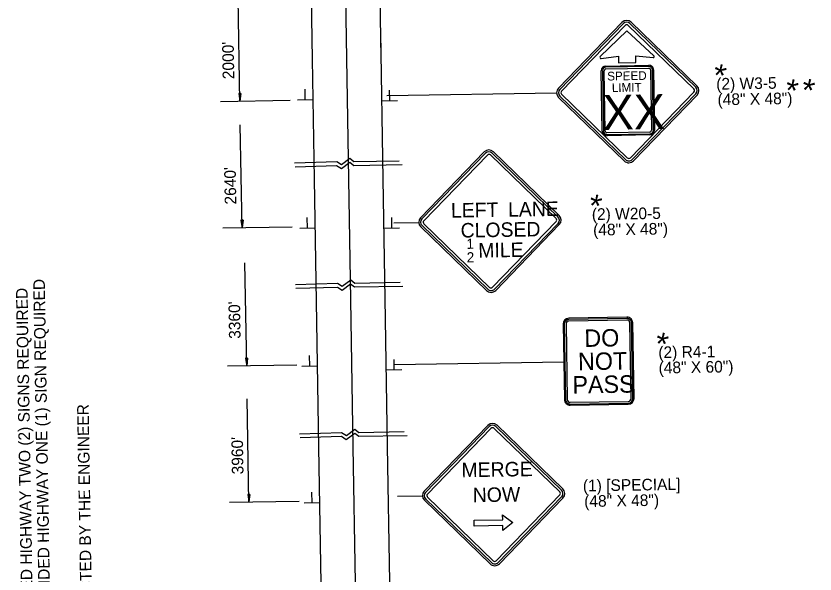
# Model space of a CAD drawing. Extents: x 1676639 to 1677883, y 226447 to 231777.
# Drawn here: x 1677053.1 to 1677466.1, y 226686.5 to 226975 of the extents above; entities that cross this region are included whole.
import ezdxf

# ---------------------------------------------------------------- set-up
doc = ezdxf.new("R2010")
doc.units = 0
for name, color, linetype in [('Default', 7, 'Continuous'), ('P_TC_Signs_Permanent', 7, 'Continuous'), ('P_TC_Signs_Temporary', 7, 'Continuous'), ('R_Annotation', 7, 'Continuous'), ('R_MOT', 7, 'Continuous')]:
    doc.layers.add(name, color=color, linetype=linetype)

msp = doc.modelspace()

# ---------------------------------------------------------------- linework, layer by layer
at = {"layer": 'Default'}
for p, q in [((1677241.81, 226953.29), (1677240.19, 227050.97)), ((1677206.35, 226952.71), (1677204.89, 227041.03)), ((1677224.08, 226953), (1677222.62, 227041.32)), ((1677168.85, 226930.99), (1677167.97, 226984.21)), ((1677242.85, 226890.55), (1677241.59, 226966.37)), ((1677207.38, 226890.65), (1677206.35, 226952.71)), ((1677225.12, 226890.6), (1677224.08, 226953)), ((1677169.36, 226934.82), (1677168.21, 226934.81)), ((1677168.21, 226934.81), (1677168.85, 226930.99)), ((1677168.31, 226934.81), (1677168.84, 226931.63)), ((1677168.4, 226934.81), (1677168.83, 226932.29)), ((1677168.5, 226934.81), (1677168.82, 226932.92)), ((1677168.6, 226934.81), (1677168.8, 226933.57)), ((1677168.69, 226934.81), (1677168.79, 226934.21)), ((1677168.87, 226934.82), (1677168.79, 226934.21)), ((1677168.97, 226934.82), (1677168.8, 226933.57)), ((1677169.07, 226934.82), (1677168.82, 226932.92)), ((1677169.16, 226934.82), (1677168.83, 226932.29)), ((1677169.26, 226934.82), (1677168.84, 226931.63)), ((1677169.36, 226934.82), (1677168.85, 226930.99)), ((1677202.65, 226931.67), (1677202.56, 226937.11)), ((1677246.29, 226931.1), (1677246.2, 226936.55)), ((1677158.86, 226930.82), (1677194.77, 226931.42)), ((1677206.62, 226931.62), (1677198.64, 226931.48)), ((1677250.26, 226931.05), (1677242.28, 226930.92)), ((1677169.93, 226865.56), (1677169.05, 226918.78)), ((1677208.43, 226827.45), (1677207.38, 226890.65)), ((1677226.15, 226828.21), (1677225.12, 226890.6)), ((1677243.87, 226828.97), (1677242.85, 226890.55)), ((1677170.44, 226869.39), (1677169.29, 226869.37)), ((1677169.29, 226869.37), (1677169.93, 226865.56)), ((1677169.39, 226869.37), (1677169.92, 226866.2)), ((1677169.49, 226869.38), (1677169.91, 226866.85)), ((1677169.58, 226869.38), (1677169.9, 226867.49)), ((1677169.68, 226869.38), (1677169.89, 226868.14)), ((1677169.78, 226869.38), (1677169.88, 226868.78)), ((1677169.96, 226869.38), (1677169.88, 226868.78)), ((1677170.05, 226869.38), (1677169.89, 226868.14)), ((1677170.15, 226869.39), (1677169.9, 226867.49)), ((1677170.25, 226869.39), (1677169.91, 226866.85)), ((1677170.35, 226869.39), (1677169.92, 226866.2)), ((1677170.44, 226869.39), (1677169.93, 226865.56)), ((1677203.75, 226865.31), (1677203.66, 226870.75)), ((1677247.38, 226865.34), (1677247.29, 226870.79)), ((1677159.95, 226865.39), (1677195.85, 226865.99)), ((1677207.72, 226865.25), (1677199.74, 226865.12)), ((1677251.35, 226865.29), (1677243.37, 226865.16)), ((1677172.34, 226794.22), (1677171.46, 226847.45)), ((1677209.68, 226752.04), (1677208.43, 226827.45)), ((1677227.41, 226752.34), (1677226.15, 226828.21)), ((1677245.14, 226752.63), (1677243.87, 226828.97)), ((1677204.93, 226793.95), (1677204.84, 226799.4)), ((1677162.35, 226794.06), (1677198.26, 226794.65)), ((1677172.85, 226798.06), (1677171.7, 226798.04)), ((1677171.7, 226798.04), (1677172.34, 226794.22)), ((1677171.8, 226798.04), (1677172.33, 226794.86)), ((1677171.89, 226798.04), (1677172.32, 226795.52)), ((1677171.99, 226798.04), (1677172.31, 226796.16)), ((1677172.09, 226798.04), (1677172.3, 226796.8)), ((1677172.18, 226798.05), (1677172.28, 226797.44)), ((1677172.36, 226798.05), (1677172.28, 226797.44)), ((1677172.46, 226798.05), (1677172.3, 226796.8)), ((1677172.56, 226798.05), (1677172.31, 226796.16)), ((1677172.66, 226798.05), (1677172.32, 226795.52)), ((1677172.75, 226798.06), (1677172.33, 226794.86)), ((1677172.85, 226798.06), (1677172.34, 226794.22)), ((1677248.59, 226792.05), (1677248.5, 226797.49)), ((1677208.9, 226793.9), (1677200.92, 226793.77)), ((1677252.56, 226792), (1677244.59, 226791.86)), ((1677173.5, 226723.85), (1677172.62, 226777.07)), ((1677210.84, 226681.67), (1677209.68, 226752.04)), ((1677228.57, 226681.96), (1677227.41, 226752.34)), ((1677246.3, 226682.26), (1677245.14, 226752.63)), ((1677206.1, 226723.33), (1677206.01, 226728.78)), ((1677163.52, 226723.68), (1677199.43, 226724.28)), ((1677174.01, 226727.68), (1677172.87, 226727.66)), ((1677172.87, 226727.66), (1677173.5, 226723.85)), ((1677172.96, 226727.67), (1677173.49, 226724.49)), ((1677173.06, 226727.67), (1677173.48, 226725.15)), ((1677173.16, 226727.67), (1677173.47, 226725.78)), ((1677173.25, 226727.67), (1677173.46, 226726.43)), ((1677173.35, 226727.67), (1677173.45, 226727.07)), ((1677173.53, 226727.68), (1677173.45, 226727.07)), ((1677173.63, 226727.68), (1677173.46, 226726.43)), ((1677173.73, 226727.68), (1677173.47, 226725.78)), ((1677173.82, 226727.68), (1677173.48, 226725.15)), ((1677173.92, 226727.68), (1677173.49, 226724.49)), ((1677174.01, 226727.68), (1677173.5, 226723.85)), ((1677210.07, 226723.28), (1677202.09, 226723.15))]:
    msp.add_line(p, q, dxfattribs=at)
for points in [[(1677197.14, 226899.07), (1677218.87, 226899.76), (1677221.36, 226898.15), (1677225.72, 226901.45), (1677227.79, 226899.78), (1677251.21, 226900.17)], [(1677197.37, 226897.04), (1677218.82, 226897.72), (1677221.31, 226896.11), (1677225.67, 226899.41), (1677227.74, 226897.74), (1677252.68, 226898.15)], [(1677197.52, 226836.23), (1677219.24, 226836.92), (1677221.73, 226835.3), (1677226.09, 226838.6), (1677228.16, 226836.94), (1677251.58, 226837.32)], [(1677197.75, 226834.2), (1677219.19, 226834.88), (1677221.68, 226833.27), (1677226.04, 226836.57), (1677228.11, 226834.9), (1677253.05, 226835.31)], [(1677199.68, 226759.06), (1677221.41, 226759.75), (1677223.9, 226758.14), (1677228.26, 226761.44), (1677230.32, 226759.77), (1677253.75, 226760.16)], [(1677199.91, 226757.03), (1677221.35, 226757.71), (1677223.84, 226756.1), (1677228.21, 226759.4), (1677230.27, 226757.73), (1677255.22, 226758.14)]]:
    msp.add_lwpolyline(points, dxfattribs=at)
at = {"layer": 'P_TC_Signs_Permanent'}
for p, q in [((1677405.03, 226938.84), (1677371.07, 226971.7)), ((1677366.3, 226971.62), (1677333.45, 226937.66)), ((1677366.98, 226970.97), (1677334.12, 226937.01)), ((1677367.92, 226970.05), (1677335.07, 226936.09)), ((1677403.47, 226937.23), (1677369.51, 226970.08)), ((1677404.38, 226938.17), (1677370.42, 226971.02)), ((1677357.96, 226949.09), (1677380.16, 226949.45)), ((1677382.6, 226947.09), (1677383.11, 226915.9)), ((1677356.12, 226915.45), (1677355.6, 226946.65)), ((1677335.09, 226934.5), (1677369.05, 226901.65)), ((1677370.64, 226901.68), (1677403.5, 226935.64)), ((1677371.59, 226900.76), (1677404.44, 226934.72)), ((1677333.53, 226932.89), (1677367.49, 226900.03)), ((1677334.18, 226933.56), (1677368.14, 226900.71)), ((1677372.26, 226900.11), (1677405.11, 226934.07)), ((1677380.76, 226913.46), (1677358.56, 226913.09)), ((1677368.83, 226819.27), (1677338.83, 226818.77)), ((1677335.88, 226815.72), (1677336.53, 226776.73)), ((1677336.48, 226815.73), (1677337.13, 226776.74)), ((1677337.38, 226815.75), (1677338.03, 226776.75)), ((1677368.84, 226818.67), (1677338.84, 226818.17)), ((1677368.85, 226817.77), (1677338.86, 226817.27)), ((1677371.02, 226777.3), (1677370.38, 226816.29)), ((1677371.92, 226777.31), (1677371.28, 226816.31)), ((1677372.52, 226777.32), (1677371.88, 226816.32)), ((1677339.55, 226775.28), (1677369.55, 226775.77)), ((1677339.57, 226774.38), (1677369.56, 226774.87)), ((1677339.58, 226773.78), (1677369.57, 226774.27))]:
    msp.add_line(p, q, dxfattribs=at)
for points in [[(1677382.82, 226954.41), (1677368.73, 226967.27), (1677355.06, 226953.95)], [(1677355.54, 226952.99), (1677364.48, 226954.26), (1677364.54, 226950.7), (1677373.53, 226950.84), (1677373.48, 226954.4), (1677382.38, 226953.44)], [(1677380.17, 226948.85), (1677369.07, 226948.67), (1677357.97, 226948.49)], [(1677357.99, 226947.59), (1677369.08, 226947.77), (1677380.18, 226947.95)], [(1677381.1, 226947.07), (1677381.62, 226915.87)], [(1677382.52, 226915.89), (1677382, 226947.08)], [(1677356.2, 226946.66), (1677356.72, 226915.46)], [(1677357.62, 226915.48), (1677357.1, 226946.67)], [(1677380.73, 226914.96), (1677358.53, 226914.59)], [(1677358.55, 226913.69), (1677380.75, 226914.06)]]:
    msp.add_lwpolyline(points, dxfattribs=at)
for centre, radius, start, end in [((1677368.73, 226969.27), 3.38, 45.9497, 135.9497), ((1677368.73, 226969.27), 2.44, 45.9497, 135.9497), ((1677368.73, 226969.27), 1.13, 45.9497, 135.9497), ((1677355.46, 226953.55), 0.563, 134.2614, 278.0747), ((1677382.44, 226954), 0.563, 263.8247, 47.6381), ((1677358, 226946.69), 2.4, 90.9497, 180.9497), ((1677358, 226946.69), 1.8, 90.9497, 180.9497), ((1677358, 226946.69), 0.9, 90.9497, 180.9497), ((1677380.2, 226947.05), 2.4, 0.9497, 90.9497), ((1677380.2, 226947.05), 1.8, 0.9497, 90.9497), ((1677380.2, 226947.05), 0.9, 0.9497, 90.9497), ((1677402.69, 226936.42), 3.38, 315.9497, 45.9497), ((1677335.88, 226935.31), 3.38, 135.9497, 225.9497), ((1677335.88, 226935.31), 2.44, 135.9497, 225.9497), ((1677335.88, 226935.31), 1.13, 135.9497, 225.9497), ((1677402.69, 226936.42), 1.13, 315.9497, 45.9497), ((1677402.69, 226936.42), 2.44, 315.9497, 45.9497), ((1677358.52, 226915.49), 2.4, 180.9497, 270.9497), ((1677358.52, 226915.49), 1.8, 180.9497, 270.9497), ((1677358.52, 226915.49), 0.9, 180.9497, 270.9497), ((1677380.72, 226915.86), 0.9, 270.9497, 0.9497), ((1677380.72, 226915.86), 1.8, 270.9497, 0.9497), ((1677380.72, 226915.86), 2.4, 270.9497, 0.9497), ((1677369.84, 226902.46), 1.13, 225.9497, 315.9497), ((1677369.84, 226902.46), 3.38, 225.9497, 315.9497), ((1677369.84, 226902.46), 2.44, 225.9497, 315.9497), ((1677368.88, 226816.27), 3, 0.9497, 90.9497), ((1677338.88, 226815.77), 3, 90.9497, 180.9497), ((1677338.88, 226815.77), 2.4, 90.9497, 180.9497), ((1677338.88, 226815.77), 1.5, 90.9497, 180.9497), ((1677368.88, 226816.27), 2.4, 0.9497, 90.9497), ((1677368.88, 226816.27), 1.5, 0.9497, 90.9497), ((1677339.53, 226776.78), 3, 180.9497, 270.9497), ((1677339.53, 226776.78), 2.4, 180.9497, 270.9497), ((1677339.53, 226776.78), 1.5, 180.9497, 270.9497), ((1677369.52, 226777.27), 1.5, 270.9497, 0.9497), ((1677369.52, 226777.27), 2.4, 270.9497, 0.9497), ((1677369.52, 226777.27), 3, 270.9497, 0.9497)]:
    msp.add_arc(centre, radius, start, end, dxfattribs=at)
at = {"layer": 'P_TC_Signs_Temporary'}
for p, q in [((1677262.24, 226870.7), (1677295.09, 226904.66)), ((1677262.91, 226870.04), (1677295.77, 226904)), ((1677263.86, 226869.13), (1677296.71, 226903.09)), ((1677298.3, 226903.12), (1677332.26, 226870.27)), ((1677299.21, 226904.06), (1677333.17, 226871.21)), ((1677299.86, 226904.74), (1677333.82, 226871.88)), ((1677332.29, 226868.68), (1677299.43, 226834.72)), ((1677296.28, 226833.07), (1677262.32, 226865.92)), ((1677296.93, 226833.75), (1677262.97, 226866.6)), ((1677297.84, 226834.69), (1677263.88, 226867.54)), ((1677333.23, 226867.76), (1677300.38, 226833.8)), ((1677333.9, 226867.11), (1677301.05, 226833.15)), ((1677296.98, 226763.37), (1677264.13, 226729.41)), ((1677297.66, 226762.71), (1677264.8, 226728.75)), ((1677298.6, 226761.8), (1677265.75, 226727.84)), ((1677334.15, 226728.98), (1677300.19, 226761.83)), ((1677335.06, 226729.92), (1677301.1, 226762.77)), ((1677335.72, 226730.59), (1677301.76, 226763.45)), ((1677264.21, 226724.63), (1677298.17, 226691.78)), ((1677264.86, 226725.31), (1677298.82, 226692.46)), ((1677265.77, 226726.25), (1677299.73, 226693.4)), ((1677301.32, 226693.43), (1677334.18, 226727.39)), ((1677302.27, 226692.51), (1677335.12, 226726.47)), ((1677302.94, 226691.86), (1677335.79, 226725.82))]:
    msp.add_line(p, q, dxfattribs=at)
for centre, radius, start, end in [((1677297.52, 226902.31), 3.38, 45.9497, 135.9497), ((1677297.52, 226902.31), 2.44, 45.9497, 135.9497), ((1677297.52, 226902.31), 1.13, 45.9497, 135.9497), ((1677264.67, 226868.35), 3.38, 135.9497, 225.9497), ((1677264.67, 226868.35), 2.44, 135.9497, 225.9497), ((1677264.67, 226868.35), 1.12, 135.9497, 225.9497), ((1677331.48, 226869.46), 1.12, 315.9497, 45.9497), ((1677331.48, 226869.46), 2.44, 315.9497, 45.9497), ((1677331.48, 226869.46), 3.38, 315.9497, 45.9497), ((1677298.63, 226835.5), 3.38, 225.9497, 315.9497), ((1677298.63, 226835.5), 2.44, 225.9497, 315.9497), ((1677298.63, 226835.5), 1.13, 225.9497, 315.9497), ((1677299.41, 226761.02), 3.38, 45.9497, 135.9497), ((1677299.41, 226761.02), 2.44, 45.9497, 135.9497), ((1677299.41, 226761.02), 1.13, 45.9497, 135.9497), ((1677266.56, 226727.06), 3.38, 135.9497, 225.9497), ((1677266.56, 226727.06), 2.44, 135.9497, 225.9497), ((1677333.37, 226728.17), 1.12, 315.9497, 45.9497), ((1677333.37, 226728.17), 2.44, 315.9497, 45.9497), ((1677333.37, 226728.17), 3.38, 315.9497, 45.9497), ((1677266.56, 226727.06), 1.12, 135.9497, 225.9497), ((1677300.52, 226694.21), 3.38, 225.9497, 315.9497), ((1677300.52, 226694.21), 2.44, 225.9497, 315.9497), ((1677300.52, 226694.21), 1.13, 225.9497, 315.9497)]:
    msp.add_arc(centre, radius, start, end, dxfattribs=at)
at = {"layer": 'R_Annotation'}
for p, q in [((1677244.84, 226933.8), (1677332.5, 226935.26)), ((1677248.36, 226868.08), (1677261.29, 226868.29)), ((1677248.55, 226794.77), (1677336.21, 226796.22)), ((1677250.25, 226726.79), (1677263.18, 226727))]:
    msp.add_line(p, q, dxfattribs=at)
at = {"layer": 'R_MOT'}
msp.add_lwpolyline([(1677304.6, 226717.08), (1677309.85, 226713.17), (1677304.73, 226709.08), (1677304.69, 226711.58), (1677289.98, 226711.34), (1677289.93, 226714.34), (1677304.64, 226714.58)], close=True, dxfattribs=at)

# ---------------------------------------------------------------- texts
at = {"layer": 'Default'}
for s, p in [("2000'", (1677165.94, 226942.33)), ("2640'", (1677167.01, 226877.55)), ("3360'", (1677169.21, 226808.14)), ("3960'", (1677170.71, 226738.08))]:
    msp.add_text(s, height=6, rotation=90.9497, dxfattribs=at).set_placement(p)
at = {"layer": 'P_TC_Signs_Permanent'}
for s, height, rotation, p in [('SPEED', 4.5, 0.9497, (1677358.69, 226941.6)), ('LIMIT', 4.5, 0.9497, (1677361.09, 226935.64)), ('XX', 18, 0.9497, (1677356.47, 226916.06)), ('DO', 9, 0.9497, (1677346.91, 226803.9)), ('NOT', 9, 0.9094, (1677343.63, 226791.85)), ('PASS', 9, 0.9497, (1677340.77, 226779.8))]:
    msp.add_text(s, height=height, rotation=rotation, dxfattribs=at).set_placement(p)
at = {"layer": 'P_TC_Signs_Temporary'}
for s, height, p in [('LEFT\u2002LANE', 7.5, (1677277.95, 226870.7)), ('CLOSED', 7.5, (1677282.96, 226860.4)), ('1', 5.25, (1677285.95, 226854.58)), (' MILE', 7.5, (1677289.29, 226850.01)), ('2', 5.25, (1677286.07, 226847.58)), ('MERGE', 7.5, (1677283.41, 226736.55)), ('NOW', 7.5, (1677289.24, 226723.63))]:
    msp.add_text(s, height=height, rotation=0.9497, dxfattribs=at).set_placement(p)
at = {"layer": 'R_Annotation'}
for s, height, rotation, p in [('*', 12, 135.9497, (1677425.57, 226951.08)), ('(2) W3-5', 6, 0.9497, (1677415.05, 226936.86)), ('*', 12, 135.9497, (1677462.74, 226943.29)), ('*', 12, 135.9497, (1677471.27, 226943.43)), ('(48" X 48")', 6, 0.9497, (1677415.73, 226928.82)), ('*', 12, 135.9497, (1677361.27, 226883.71)), ('(2) W20-5', 6, 0.9497, (1677350.75, 226869.5)), ('(48" X 48")', 6, 0.9497, (1677351.43, 226861.45)), ('SOUTHBOUND UNDIVIDED HIGHWAY ONE (1) SIGN REQUIRED', 6, 90.9497, (1677072.02, 226597.08)), ('NORTHBOUND DIVIDED HIGHWAY TWO (2) SIGNS REQUIRED ', 6, 90.9497, (1677063.03, 226596.94)), ('*', 12, 135.9497, (1677395.65, 226812.34)), ('(2) R4-1', 6, 0.9497, (1677385.13, 226798.12)), ('(48" X 60")', 6, 0.9497, (1677385.26, 226790.18)), ('IF AND WHERE DIRECTED BY THE ENGINEER', 6, 90.9497, (1677093.61, 226597.44)), ('(1) [SPECIAL]', 6, 0.9497, (1677346.13, 226729.21)), ('(48" X 48")', 6, 0.9497, (1677346.81, 226721.17))]:
    msp.add_text(s, height=height, rotation=rotation, dxfattribs=at).set_placement(p)

doc.saveas('drawing.dxf')
